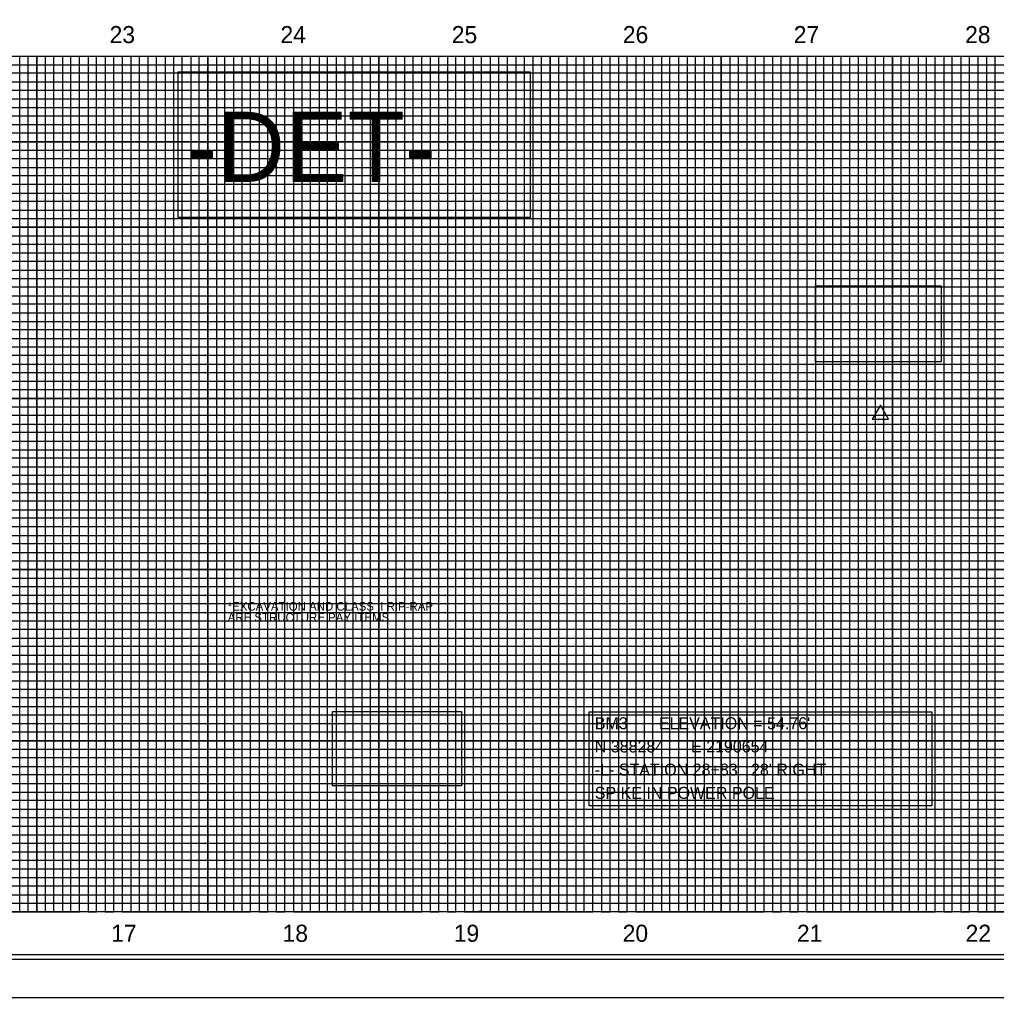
# Model space of a CAD drawing. Extents: x 1019474 to 1021161, y 504129 to 505324.
# Drawn here: x 1020231 to 1020802, y 504129 to 504701 of the extents above; entities that cross this region are included whole.
import ezdxf

# ---------------------------------------------------------------- set-up
doc = ezdxf.new("R2010")
doc.units = 0
for name, color, linetype in [('Default', 7, 'Continuous'), ('Exist Vertical Profile Horizontal Axis Label Major', 7, 'Continuous'), ('Prop Grid Mask', 7, 'Continuous'), ('Prop Vertical Profile Curve Label', 7, 'Continuous'), ('Prop VPI Label', 7, 'Continuous'), ('Sheet Cutting Line CELL', 7, 'Continuous'), ('Sheet DOT Grid CELL', 7, 'Continuous'), ('Sheet Layout Profile Border Port 2', 7, 'Continuous'), ('Sheet Plot Border Inside CELL', 7, 'Continuous'), ('Sheet Plot Border Outside CELL', 7, 'Continuous'), ('Sheet Profile CELL', 7, 'Continuous'), ('Sheet Profile Grid Major CELL', 7, 'Continuous'), ('Sheet Profile Grid Middle CELL', 7, 'Continuous'), ('Sheet Profile Grid Minor CELL', 7, 'Continuous')]:
    doc.layers.add(name, color=color, linetype=linetype)

msp = doc.modelspace()

# ---------------------------------------------------------------- linework, layer by layer
at = {"layer": 'Prop Grid Mask'}
for points in [[(1020323.82, 504670.08), (1020529.5, 504670.08), (1020529.5, 504584.93), (1020323.82, 504584.93)], [(1020696.35, 504545.08), (1020769.69, 504545.08), (1020769.69, 504500.71), (1020696.35, 504500.71)], [(1020414.04, 504296.41), (1020489.5, 504296.41), (1020489.5, 504253), (1020414.04, 504253)], [(1020564.06, 504296.22), (1020764.34, 504296.22), (1020764.34, 504241.33), (1020564.06, 504241.33)]]:
    msp.add_lwpolyline(points, close=True, dxfattribs=at)
at = {"layer": 'Prop Vertical Profile Curve Label'}
msp.add_lwpolyline([(1020729.46, 504467.19), (1020738.98, 504467.19), (1020734.22, 504475.44)], close=True, dxfattribs=at)
at = {"layer": 'Sheet Cutting Line CELL'}
msp.add_line((1019474.22, 504129.29), (1021158.22, 504129.29), dxfattribs=at)
at = {"layer": 'Sheet DOT Grid CELL'}
for p, q in [((1019641.22, 504679.29), (1021141.11, 504679.29)), ((1020241.22, 504679.29), (1020241.22, 504179.29)), ((1020291.22, 504679.29), (1020291.22, 504179.29)), ((1020341.22, 504679.29), (1020341.22, 504179.29)), ((1020391.22, 504679.29), (1020391.22, 504179.29)), ((1020441.22, 504679.29), (1020441.22, 504179.29)), ((1020491.22, 504679.29), (1020491.22, 504179.29)), ((1020541.22, 504679.29), (1020541.22, 504179.29)), ((1020591.22, 504679.29), (1020591.22, 504179.29)), ((1020641.22, 504679.29), (1020641.22, 504179.29)), ((1020691.22, 504679.29), (1020691.22, 504179.29)), ((1020741.22, 504679.29), (1020741.22, 504179.29)), ((1020791.22, 504679.29), (1020791.22, 504179.29)), ((1019641.22, 504629.29), (1021141.11, 504629.29)), ((1019641.22, 504579.29), (1021141.11, 504579.29)), ((1019641.22, 504529.29), (1021141.11, 504529.29)), ((1019641.22, 504479.29), (1021141.11, 504479.29)), ((1019641.22, 504429.29), (1021141.11, 504429.29)), ((1019641.22, 504379.29), (1021141.11, 504379.29)), ((1019641.22, 504329.29), (1021141.11, 504329.29)), ((1019641.22, 504279.29), (1021141.11, 504279.29)), ((1019641.22, 504229.29), (1021141.11, 504229.29))]:
    msp.add_line(p, q, dxfattribs=at)
at = {"layer": 'Sheet Layout Profile Border Port 2'}
msp.add_lwpolyline([(1019691.22, 504679.29), (1021091.22, 504679.29), (1021091.22, 504179.29), (1019691.22, 504179.29)], close=True, dxfattribs=at)
at = {"layer": 'Sheet Plot Border Inside CELL'}
msp.add_lwpolyline([(1019487.22, 504151.74), (1021153.72, 504151.74), (1021153.72, 505206.84), (1019487.22, 505206.84)], close=True, dxfattribs=at)
at = {"layer": 'Sheet Plot Border Outside CELL'}
msp.add_lwpolyline([(1019474.22, 504129.29), (1021158.22, 504129.29), (1021158.22, 505229.29), (1019474.22, 505229.29)], close=True, dxfattribs=at)
at = {"layer": 'Sheet Profile CELL'}
for p, q in [((1019641.22, 504679.29), (1021141.22, 504679.29)), ((1021141.22, 504179.29), (1019641.22, 504179.29)), ((1019641.22, 504154.29), (1021141.22, 504154.29))]:
    msp.add_line(p, q, dxfattribs=at)
msp.add_lwpolyline([(1021141.22, 505204.29), (1019641.22, 505204.29), (1019641.22, 504154.29), (1021141.22, 504154.29)], close=True, dxfattribs=at)
at = {"layer": 'Sheet Profile Grid Major CELL'}
for p, q in [((1020241.22, 504679.29), (1020291.22, 504679.29)), ((1020341.22, 504679.29), (1020391.22, 504679.29)), ((1020441.22, 504679.29), (1020491.22, 504679.29)), ((1020541.22, 504679.29), (1020591.22, 504679.29)), ((1020641.22, 504679.29), (1020691.22, 504679.29)), ((1020741.22, 504679.29), (1020791.22, 504679.29))]:
    msp.add_line(p, q, dxfattribs=at)
for points in [[(1020191.22, 504179.29), (1020241.22, 504179.29), (1020241.22, 504679.29), (1020291.22, 504679.29), (1020291.22, 504179.29), (1020341.22, 504179.29), (1020341.22, 504679.29), (1020391.22, 504679.29), (1020391.22, 504179.29), (1020441.22, 504179.29), (1020441.22, 504679.29), (1020491.22, 504679.29), (1020491.22, 504179.29), (1020541.22, 504179.29), (1020541.22, 504679.29), (1020591.22, 504679.29), (1020591.22, 504179.29), (1020641.22, 504179.29), (1020641.22, 504679.29), (1020691.22, 504679.29), (1020691.22, 504179.29), (1020741.22, 504179.29), (1020741.22, 504679.29), (1020791.22, 504679.29), (1020791.22, 504179.29), (1020841.22, 504179.29)], [(1021141.22, 504629.29), (1019641.22, 504629.29)], [(1021141.22, 504579.29), (1019641.22, 504579.29), (1019641.22, 504529.29), (1021141.22, 504529.29)], [(1021141.22, 504479.29), (1019641.22, 504479.29), (1019641.22, 504429.29), (1021141.22, 504429.29)], [(1021141.22, 504379.29), (1019641.22, 504379.29), (1019641.22, 504329.29), (1021141.22, 504329.29)], [(1021141.22, 504279.29), (1019641.22, 504279.29), (1019641.22, 504279.29), (1019641.22, 504229.29), (1021141.22, 504229.29)], [(1021141.22, 504179.29), (1019641.22, 504179.29)]]:
    msp.add_lwpolyline(points, dxfattribs=at)
at = {"layer": 'Sheet Profile Grid Middle CELL'}
for points in [[(1020216.22, 504179.29), (1020266.22, 504179.29), (1020266.22, 504179.29), (1020266.22, 504679.29), (1020316.22, 504679.29), (1020316.22, 504179.29), (1020366.22, 504179.29), (1020366.22, 504679.29), (1020416.22, 504679.29), (1020416.22, 504179.29), (1020466.22, 504179.29), (1020466.22, 504679.29), (1020516.22, 504679.29), (1020516.22, 504179.29), (1020566.22, 504179.29), (1020566.22, 504679.29), (1020616.22, 504679.29), (1020616.22, 504179.29), (1020666.22, 504179.29), (1020666.22, 504679.29), (1020716.22, 504679.29), (1020716.22, 504179.29), (1020766.22, 504179.29), (1020766.22, 504679.29), (1020816.22, 504679.29)], [(1019641.22, 504654.29), (1021141.22, 504654.29)], [(1021141.22, 504604.29), (1019641.22, 504604.29), (1019641.22, 504554.29), (1021141.22, 504554.29)], [(1021141.22, 504504.29), (1019641.22, 504504.29), (1019641.22, 504454.29), (1021141.22, 504454.29)], [(1021141.22, 504404.29), (1019641.22, 504404.29), (1019641.22, 504354.29), (1021141.22, 504354.29)], [(1021141.22, 504304.29), (1019641.22, 504304.29), (1019641.22, 504254.29), (1021141.22, 504254.29)], [(1021141.22, 504204.29), (1019641.22, 504204.29)]]:
    msp.add_lwpolyline(points, dxfattribs=at)
at = {"layer": 'Sheet Profile Grid Minor CELL'}
for p, q in [((1019691.22, 504674.29), (1021091.22, 504674.29)), ((1021091.22, 504669.29), (1019691.22, 504669.29)), ((1019691.22, 504664.29), (1021091.22, 504664.29)), ((1021091.22, 504659.29), (1019691.22, 504659.29)), ((1019691.22, 504649.29), (1021091.22, 504649.29)), ((1021091.22, 504644.29), (1019691.22, 504644.29)), ((1019691.22, 504639.29), (1021091.22, 504639.29)), ((1021091.22, 504634.29), (1019691.22, 504634.29)), ((1019691.22, 504624.29), (1021091.22, 504624.29)), ((1021091.22, 504619.29), (1019691.22, 504619.29)), ((1019691.22, 504614.29), (1021091.22, 504614.29)), ((1021091.22, 504609.29), (1019691.22, 504609.29)), ((1019691.22, 504599.29), (1021091.22, 504599.29)), ((1021091.22, 504594.29), (1019691.22, 504594.29)), ((1019691.22, 504589.29), (1021091.22, 504589.29)), ((1021091.22, 504584.29), (1019691.22, 504584.29)), ((1019691.22, 504574.29), (1021091.22, 504574.29)), ((1021091.22, 504569.29), (1019691.22, 504569.29)), ((1019691.22, 504564.29), (1021091.22, 504564.29)), ((1021091.22, 504559.29), (1019691.22, 504559.29)), ((1019691.22, 504549.29), (1021091.22, 504549.29)), ((1021091.22, 504544.29), (1019691.22, 504544.29)), ((1019691.22, 504539.29), (1021091.22, 504539.29)), ((1021091.22, 504534.29), (1019691.22, 504534.29)), ((1019691.22, 504524.29), (1021091.22, 504524.29)), ((1021091.22, 504519.29), (1019691.22, 504519.29)), ((1019691.22, 504514.29), (1021091.22, 504514.29)), ((1021091.22, 504509.29), (1019691.22, 504509.29)), ((1019691.22, 504499.29), (1021091.22, 504499.29)), ((1021091.22, 504494.29), (1019691.22, 504494.29)), ((1019691.22, 504489.29), (1021091.22, 504489.29)), ((1021091.22, 504484.29), (1019691.22, 504484.44)), ((1019691.22, 504474.29), (1021091.22, 504474.29)), ((1021091.22, 504469.29), (1019691.22, 504469.29)), ((1019691.22, 504464.29), (1021091.22, 504464.29)), ((1021091.22, 504459.29), (1019691.22, 504459.29)), ((1019691.22, 504449.29), (1021091.22, 504449.29)), ((1021091.22, 504444.29), (1019691.22, 504444.29)), ((1019691.22, 504439.29), (1021091.22, 504439.29)), ((1021091.22, 504434.29), (1019691.22, 504434.29)), ((1019691.22, 504424.29), (1021091.22, 504424.29)), ((1021091.22, 504419.29), (1019691.22, 504419.29)), ((1019691.22, 504414.29), (1021091.22, 504414.29)), ((1021091.22, 504409.29), (1019691.22, 504409.29)), ((1019691.22, 504399.29), (1021091.22, 504399.29)), ((1021091.22, 504394.29), (1019691.22, 504394.29)), ((1019691.22, 504389.29), (1021091.22, 504389.29)), ((1021091.22, 504384.29), (1019691.22, 504384.29)), ((1019691.22, 504374.29), (1021091.22, 504374.29)), ((1021091.22, 504369.29), (1019691.22, 504369.29)), ((1019691.22, 504364.29), (1021091.22, 504364.29)), ((1021091.22, 504359.29), (1019691.22, 504359.29)), ((1019691.22, 504349.29), (1021091.22, 504349.29)), ((1021091.22, 504344.29), (1019691.22, 504344.29)), ((1019691.22, 504339.29), (1021091.22, 504339.29)), ((1021091.22, 504334.29), (1019691.22, 504334.29)), ((1019691.22, 504324.29), (1021091.22, 504324.29)), ((1021091.22, 504319.29), (1019691.22, 504319.29)), ((1019691.22, 504314.29), (1021091.22, 504314.29)), ((1021091.22, 504309.29), (1019691.22, 504309.29)), ((1019691.22, 504299.29), (1021091.22, 504299.29)), ((1021091.22, 504294.29), (1019691.22, 504294.29)), ((1019691.22, 504289.29), (1021091.22, 504289.29)), ((1021091.22, 504284.29), (1019691.22, 504284.29)), ((1019691.22, 504274.29), (1020891.22, 504274.29)), ((1020891.22, 504269.29), (1019691.22, 504269.29)), ((1019691.22, 504264.29), (1020891.22, 504264.29)), ((1020891.22, 504259.29), (1019691.22, 504259.29)), ((1019691.22, 504249.29), (1021091.22, 504249.29)), ((1021091.22, 504244.29), (1019691.22, 504244.29)), ((1019691.22, 504239.29), (1021091.22, 504239.29)), ((1021091.22, 504234.29), (1019691.22, 504234.29)), ((1019691.22, 504224.29), (1021091.22, 504224.29)), ((1021091.22, 504219.29), (1019691.22, 504219.29)), ((1019691.22, 504214.29), (1021091.22, 504214.29)), ((1021091.22, 504209.29), (1019691.22, 504209.29)), ((1019691.22, 504199.29), (1021091.22, 504199.29)), ((1021091.22, 504194.29), (1019691.22, 504194.29)), ((1019691.22, 504189.29), (1021091.22, 504189.29)), ((1019691.22, 504184.29), (1021091.22, 504184.29))]:
    msp.add_line(p, q, dxfattribs=at)
for points in [[(1020226.22, 504679.29), (1020231.22, 504679.29), (1020231.22, 504179.29), (1020236.22, 504179.29), (1020236.22, 504679.29), (1020246.22, 504679.29), (1020246.22, 504179.29), (1020251.22, 504179.29), (1020251.22, 504679.29), (1020256.22, 504679.29), (1020256.22, 504179.29), (1020261.22, 504179.29), (1020261.22, 504679.29), (1020271.22, 504679.29), (1020271.22, 504179.29), (1020276.22, 504179.29), (1020276.22, 504679.29), (1020281.22, 504679.29), (1020281.22, 504179.29), (1020286.22, 504179.29), (1020286.22, 504679.29), (1020296.22, 504679.29), (1020296.22, 504179.29), (1020301.22, 504179.29), (1020301.22, 504679.29), (1020306.22, 504679.29), (1020306.22, 504179.29), (1020311.22, 504179.29), (1020311.22, 504679.29), (1020321.22, 504679.29), (1020321.22, 504179.29), (1020326.22, 504179.29), (1020326.22, 504679.29), (1020331.22, 504679.29), (1020331.22, 504179.29), (1020336.22, 504179.29), (1020336.22, 504679.29), (1020346.22, 504679.29), (1020346.22, 504179.29), (1020346.22, 504179.29), (1020351.22, 504179.29), (1020351.22, 504679.29), (1020356.22, 504679.29), (1020356.22, 504179.29), (1020361.22, 504179.29), (1020361.22, 504679.29), (1020371.22, 504679.29), (1020371.22, 504179.29), (1020376.22, 504179.29), (1020376.22, 504679.29), (1020381.22, 504679.29), (1020381.22, 504179.29), (1020386.22, 504179.29), (1020386.22, 504679.29), (1020396.22, 504679.29), (1020396.22, 504179.29), (1020401.22, 504179.29), (1020401.22, 504679.29), (1020406.22, 504679.29), (1020406.22, 504179.29), (1020411.22, 504179.29), (1020411.22, 504679.29), (1020421.22, 504679.29), (1020421.22, 504179.29), (1020426.22, 504179.29), (1020426.22, 504679.29), (1020431.22, 504679.29), (1020431.22, 504179.29), (1020436.22, 504179.29), (1020436.22, 504679.29), (1020446.22, 504679.29), (1020446.22, 504179.29), (1020451.22, 504179.29), (1020451.22, 504679.29), (1020456.22, 504679.29), (1020456.22, 504179.29), (1020461.22, 504179.29), (1020461.22, 504679.29), (1020471.22, 504679.29), (1020471.22, 504179.29), (1020476.22, 504179.29), (1020476.22, 504679.29), (1020481.22, 504679.29), (1020481.22, 504179.29), (1020486.22, 504179.29), (1020486.22, 504679.29), (1020496.22, 504679.29), (1020496.22, 504179.29), (1020500.92, 504179.84), (1020501.22, 504179.29), (1020501.22, 504679.29), (1020506.22, 504679.29), (1020506.22, 504179.29), (1020511.22, 504179.29), (1020511.22, 504679.29), (1020521.22, 504679.29), (1020521.22, 504179.29), (1020526.22, 504179.29)], [(1020526.22, 504179.29), (1020526.22, 504679.29), (1020531.22, 504679.29), (1020531.22, 504179.29), (1020536.22, 504179.29), (1020536.22, 504679.29), (1020546.22, 504679.29), (1020546.22, 504179.29), (1020551.22, 504179.29), (1020551.22, 504679.29), (1020556.22, 504679.29), (1020556.22, 504179.29), (1020561.22, 504179.29), (1020561.22, 504679.29), (1020571.22, 504679.29), (1020571.22, 504179.29), (1020576.22, 504179.29), (1020576.22, 504679.29), (1020581.22, 504679.29), (1020581.22, 504179.29), (1020586.22, 504179.29), (1020586.22, 504679.29), (1020596.22, 504679.29), (1020596.22, 504179.29), (1020601.22, 504179.29), (1020601.22, 504679.29), (1020606.22, 504679.29), (1020606.22, 504179.29), (1020611.22, 504179.29), (1020611.22, 504679.29), (1020621.22, 504679.29), (1020621.22, 504179.29), (1020626.22, 504179.29), (1020626.22, 504679.29), (1020631.22, 504679.29), (1020631.22, 504179.29), (1020636.22, 504179.29), (1020636.22, 504679.29), (1020646.22, 504679.29), (1020646.22, 504179.29), (1020651.22, 504179.29), (1020651.22, 504679.29), (1020656.22, 504679.29), (1020656.22, 504179.29), (1020661.22, 504179.29), (1020661.22, 504679.29), (1020671.22, 504679.29), (1020671.22, 504179.29), (1020676.22, 504179.29), (1020676.22, 504679.29), (1020681.22, 504679.29), (1020681.22, 504179.29), (1020686.22, 504179.29), (1020686.22, 504679.29), (1020696.22, 504679.29), (1020696.22, 504179.29), (1020701.22, 504179.29), (1020701.22, 504679.29), (1020706.22, 504679.29), (1020706.22, 504179.29), (1020711.22, 504179.29), (1020711.22, 504679.29), (1020721.22, 504679.29), (1020721.22, 504179.29), (1020726.22, 504179.29), (1020726.22, 504679.29), (1020731.22, 504679.29), (1020731.22, 504179.29), (1020736.22, 504179.29), (1020736.22, 504679.29), (1020746.22, 504679.29), (1020746.22, 504179.29), (1020751.22, 504179.29), (1020751.22, 504679.29), (1020756.22, 504679.29), (1020756.22, 504179.29), (1020761.22, 504179.29), (1020761.22, 504679.29), (1020771.22, 504679.29), (1020771.22, 504179.29), (1020776.22, 504179.29), (1020776.22, 504679.29), (1020781.22, 504679.29), (1020781.22, 504179.29), (1020786.22, 504179.29), (1020786.22, 504679.29), (1020796.22, 504679.29), (1020796.22, 504179.29), (1020801.22, 504179.29), (1020801.22, 504679.29), (1020806.22, 504679.29)]]:
    msp.add_lwpolyline(points, dxfattribs=at)

# ---------------------------------------------------------------- texts
at = {"layer": 'Default'}
for s, p in [('*EXCAVATION AND CLASS II RIP-RAP', (1020352.83, 504355.3)), ('ARE STRUCTURE PAY ITEMS', (1020352.83, 504348.87))]:
    msp.add_text(s, height=5, rotation=360, dxfattribs=at).set_placement(p)
at = {"layer": 'Exist Vertical Profile Horizontal Axis Label Major'}
for s, p in [('23', (1020283.83, 504686.86)), ('24', (1020383.67, 504686.86)), ('25', (1020483.77, 504686.86)), ('26', (1020583.71, 504686.86)), ('27', (1020683.56, 504686.86)), ('28', (1020783.69, 504686.86)), ('17', (1020284.76, 504161.79)), ('18', (1020384.89, 504161.79)), ('19', (1020484.93, 504161.79)), ('20', (1020583.61, 504161.79)), ('21', (1020685.45, 504161.79)), ('22', (1020784, 504161.79))]:
    msp.add_text(s, height=10, dxfattribs=at).set_placement(p)
at = {"layer": 'Prop VPI Label'}
for s, height, p in [('-DET-', 40.95, (1020328.53, 504605.83)), ("BM3       ELEVATION = 54.76'", 7, (1020567.33, 504286.01)), ('N 388284      E 2190654', 7, (1020567.33, 504272.45)), ("-L- STATION 28+83   28' RIGHT", 7, (1020567.33, 504258.89)), ('SPIKE IN POWER POLE', 7, (1020567.33, 504245.32))]:
    msp.add_text(s, height=height, dxfattribs=at).set_placement(p)

doc.saveas('drawing.dxf')
